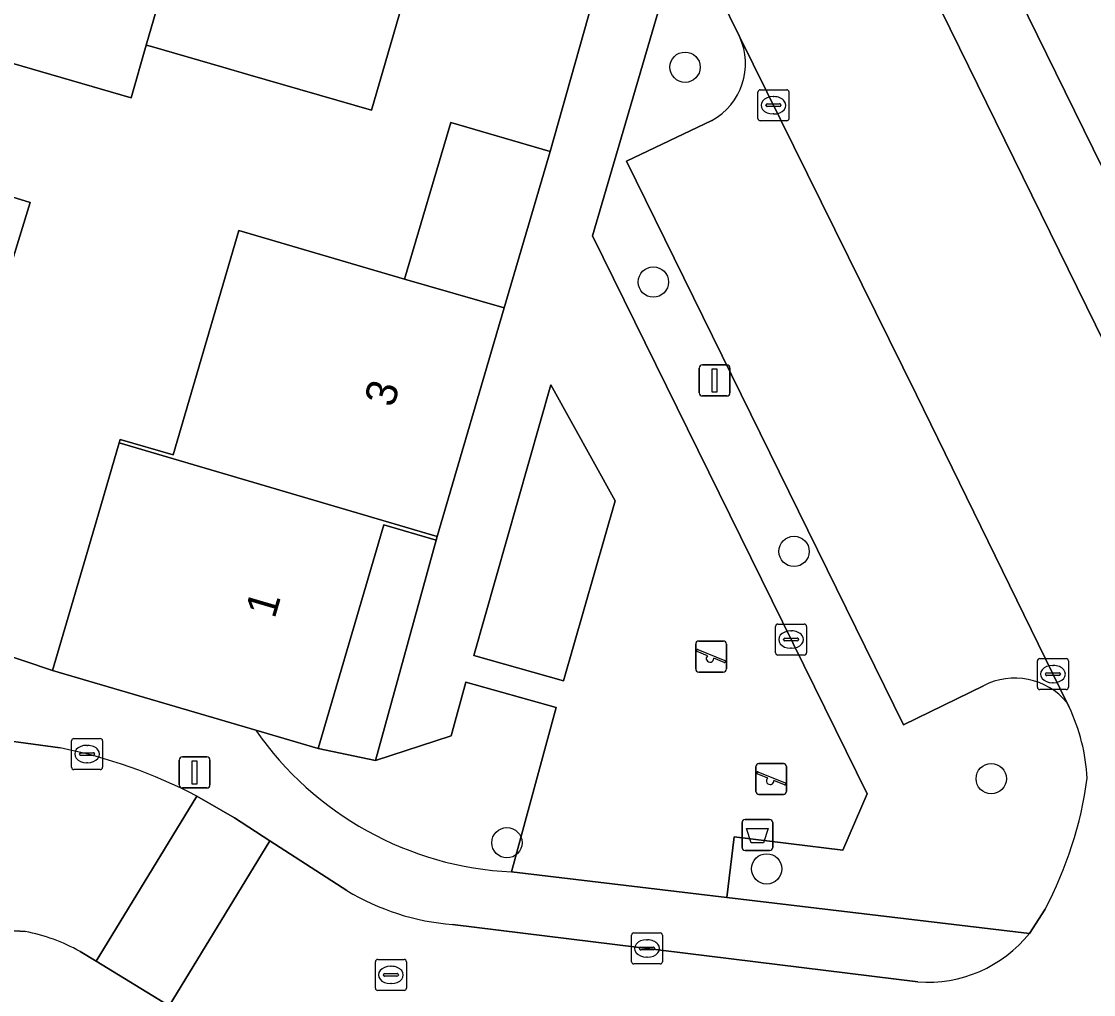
# Model space of a CAD drawing. Extents: x 159716 to 160783, y 383290 to 384031.
# Drawn here: x 160051.81 to 160086.41, y 383383.96 to 383415.36 of the extents above; entities that cross this region are included whole.
import ezdxf

# ---------------------------------------------------------------- set-up
doc = ezdxf.new("R2010")
doc.units = 0
for name, color, linetype in [('IMGEO_Afvalbak', 7, 'Continuous'), ('IMGEO_Boom', 7, 'Continuous'), ('IMGEO_Erf', 7, 'Continuous'), ('IMGEO_Groenvoorziening', 7, 'Continuous'), ('IMGEO_Kolk', 7, 'Continuous'), ('IMGEO_Lichtmast', 7, 'Continuous'), ('IMGEO_Pand', 7, 'Continuous'), ('IMGEO_Pand_nummerreeks', 7, 'Continuous'), ('IMGEO_Parkeervlak_open', 7, 'Continuous'), ('IMGEO_Rijbaan_lokaal_open', 7, 'Continuous'), ('IMGEO_Rioolput', 7, 'Continuous'), ('IMGEO_Speelvoorziening', 7, 'Continuous'), ('IMGEO_Voetpad_open', 7, 'Continuous')]:
    doc.layers.add(name, color=color, linetype=linetype)

msp = doc.modelspace()

# ---------------------------------------------------------------- linework, layer by layer
at = {"layer": 'IMGEO_Afvalbak'}
for p, q in [((160075.166, 383389.612), (160075.956, 383389.612)), ((160075.956, 383389.612), (160075.166, 383389.612)), ((160075.066, 383388.712), (160075.066, 383389.512)), ((160075.066, 383389.512), (160075.066, 383388.712)), ((160076.056, 383389.512), (160076.056, 383388.712)), ((160076.056, 383388.712), (160076.056, 383389.512)), ((160075.956, 383388.612), (160075.166, 383388.612)), ((160075.166, 383388.612), (160075.956, 383388.612))]:
    msp.add_line(p, q, dxfattribs=at)
msp.add_lwpolyline([(160075.209, 383389.326), (160075.913, 383389.326), (160075.764, 383388.856), (160075.358, 383388.856), (160075.209, 383389.326)], dxfattribs=at)
for centre, start, end in [((160075.166, 383389.512), 90, 180), ((160075.166, 383389.512), 90, 180), ((160075.956, 383389.512), 0, 90), ((160075.956, 383389.512), 360, 90), ((160075.166, 383388.712), 180, 270), ((160075.166, 383388.712), 180, 270), ((160075.956, 383388.712), 270, 0), ((160075.956, 383388.712), 270, 0)]:
    msp.add_arc(centre, 0.1, start, end, dxfattribs=at)
at = {"layer": 'IMGEO_Boom'}
for centre in [(160073.229, 383413.882), (160072.206, 383406.951), (160076.745, 383398.261), (160083.107, 383390.929), (160067.48, 383388.863), (160075.861, 383388.02)]:
    msp.add_circle(centre, 0.489, dxfattribs=at)
at = {"layer": 'IMGEO_Erf'}
for points in [[(160080.405, 383423.453), (160097.768, 383388.109)], [(160044.548, 383397.2), (160052.814, 383394.42), (160054.222, 383399.218), (160054.969, 383401.761), (160055.002, 383401.874), (160056.707, 383401.373), (160058.832, 383408.61), (160064.175, 383407.042), (160065.671, 383412.098), (160068.88, 383411.166), (160070.627, 383417.38), (160068.099, 383420.349), (160065.601, 383421.083), (160063.114, 383412.492), (160059.121, 383413.649), (160058.312, 383413.883), (160056.011, 383414.549), (160055.843, 383414.597), (160055.35, 383412.897), (160053.1, 383413.548), (160048.31, 383414.935)], [(160048.536, 383410.614), (160052.099, 383409.518), (160051.183, 383406.541)]]:
    msp.add_lwpolyline(points, dxfattribs=at)
msp.add_lwpolyline([(160065.195, 383398.622), (160063.506, 383399.118), (160061.388, 383391.903), (160063.239, 383391.511)], close=True, dxfattribs=at)
at = {"layer": 'IMGEO_Groenvoorziening'}
for points in [[(160074.989, 383414.871), (160074.348, 383416.169), (160073.789, 383417.331), (160072.664, 383416.709), (160070.246, 383408.439), (160079.102, 383390.437), (160078.317, 383388.621), (160074.813, 383389.05), (160074.573, 383387.094), (160084.344, 383385.936), (160084.845, 383386.721)], [(160082.854, 383393.924), (160080.28, 383392.663), (160071.343, 383410.855), (160074.095, 383412.165)], [(160067.629, 383387.921), (160069.074, 383393.223), (160066.154, 383394.043), (160065.679, 383392.313), (160063.239, 383391.511), (160061.388, 383391.903), (160059.374, 383392.494)], [(160085.62, 383393.242), (160085.552, 383393.382)]]:
    msp.add_lwpolyline(points, dxfattribs=at)
msp.add_lwpolyline([(160069.303, 383394.089), (160070.972, 383399.888), (160068.898, 383403.633), (160066.412, 383394.899)], close=True, dxfattribs=at)
for centre, radius, start, end in [((160073.094, 383413.996), 2.087, 298.6507, 24.7846), ((160083.869, 383391.993), 2.182, 39.5467, 117.7354), ((160080.182, 383390.64), 6.028, 2.8628, 25.5727), ((160068.137, 383398.575), 10.666, 214.7589, 267.2711), ((160073.9, 383392.571), 12.41, 331.8731, 352.4505)]:
    msp.add_arc(centre, radius, start, end, dxfattribs=at)
at = {"layer": 'IMGEO_Kolk'}
for p, q in [((160075.581, 383412.227), (160075.581, 383413.079)), ((160075.656, 383413.153), (160076.508, 383413.153)), ((160076.582, 383413.079), (160076.582, 383412.227)), ((160075.883, 383412.696), (160076.281, 383412.696)), ((160076.069, 383412.933), (160076.094, 383412.933)), ((160075.84, 383412.647), (160075.84, 383412.659)), ((160076.278, 383412.61), (160075.88, 383412.61)), ((160076.092, 383412.373), (160076.067, 383412.373)), ((160076.324, 383412.659), (160076.324, 383412.647)), ((160076.508, 383412.153), (160075.656, 383412.153)), ((160076.15, 383394.991), (160076.15, 383395.843)), ((160076.225, 383395.917), (160077.077, 383395.917)), ((160077.151, 383395.843), (160077.151, 383394.991)), ((160076.409, 383395.411), (160076.409, 383395.423)), ((160076.452, 383395.46), (160076.85, 383395.46)), ((160076.638, 383395.697), (160076.663, 383395.697)), ((160076.893, 383395.423), (160076.893, 383395.411)), ((160076.847, 383395.374), (160076.449, 383395.374)), ((160076.661, 383395.137), (160076.636, 383395.137)), ((160077.077, 383394.917), (160076.225, 383394.917)), ((160084.598, 383393.877), (160084.598, 383394.729)), ((160084.673, 383394.803), (160085.525, 383394.803)), ((160085.599, 383394.729), (160085.599, 383393.877)), ((160085.086, 383394.583), (160085.111, 383394.583)), ((160084.857, 383394.297), (160084.857, 383394.309)), ((160085.295, 383394.26), (160084.897, 383394.26)), ((160084.9, 383394.346), (160085.298, 383394.346)), ((160085.109, 383394.023), (160085.084, 383394.023)), ((160085.341, 383394.309), (160085.341, 383394.297)), ((160085.525, 383393.803), (160084.673, 383393.803)), ((160053.433, 383391.298), (160053.433, 383392.15)), ((160053.508, 383392.224), (160054.36, 383392.224)), ((160053.921, 383392.004), (160053.946, 383392.004)), ((160054.434, 383392.15), (160054.434, 383391.298)), ((160053.692, 383391.718), (160053.692, 383391.73)), ((160054.13, 383391.681), (160053.732, 383391.681)), ((160053.735, 383391.767), (160054.133, 383391.767)), ((160054.176, 383391.73), (160054.176, 383391.718)), ((160053.944, 383391.444), (160053.919, 383391.444)), ((160054.36, 383391.224), (160053.508, 383391.224)), ((160071.5, 383385.025), (160071.5, 383385.877)), ((160071.575, 383385.951), (160072.427, 383385.951)), ((160071.988, 383385.731), (160072.013, 383385.731)), ((160072.501, 383385.877), (160072.501, 383385.025)), ((160071.759, 383385.445), (160071.759, 383385.457)), ((160072.197, 383385.408), (160071.799, 383385.408)), ((160071.802, 383385.494), (160072.2, 383385.494)), ((160072.243, 383385.457), (160072.243, 383385.445)), ((160072.011, 383385.171), (160071.986, 383385.171)), ((160072.427, 383384.951), (160071.575, 383384.951))]:
    msp.add_line(p, q, dxfattribs=at)
for points in [[(160075.581, 383412.227), (160075.581, 383413.079)], [(160075.656, 383413.153), (160076.508, 383413.153)], [(160076.582, 383413.079), (160076.582, 383412.227)], [(160076.508, 383412.153), (160075.656, 383412.153)], [(160076.15, 383394.991), (160076.15, 383395.843)], [(160076.225, 383395.917), (160077.077, 383395.917)], [(160077.151, 383395.843), (160077.151, 383394.991)], [(160077.077, 383394.917), (160076.225, 383394.917)], [(160084.598, 383393.877), (160084.598, 383394.729)], [(160084.673, 383394.803), (160085.525, 383394.803)], [(160085.599, 383394.729), (160085.599, 383393.877)], [(160085.525, 383393.803), (160084.673, 383393.803)], [(160053.433, 383391.298), (160053.433, 383392.15)], [(160053.508, 383392.224), (160054.36, 383392.224)], [(160054.434, 383392.15), (160054.434, 383391.298)], [(160054.36, 383391.224), (160053.508, 383391.224)], [(160071.5, 383385.025), (160071.5, 383385.877)], [(160071.575, 383385.951), (160072.427, 383385.951)], [(160072.501, 383385.877), (160072.501, 383385.025)], [(160072.427, 383384.951), (160071.575, 383384.951)]]:
    msp.add_lwpolyline(points, dxfattribs=at)
for centre, radius, start, end in [((160075.658, 383413.077), 0.0765, 91.552, 178.448), ((160075.658, 383413.077), 0.0765, 91.552, 178.448), ((160076.506, 383413.077), 0.0765, 1.552, 88.448), ((160076.506, 383413.077), 0.0765, 1.552, 88.448), ((160075.88, 383412.656), 0.0403, 85.8775, 175.7526), ((160076.285, 383412.658), 0.0386, 1.7309, 96.639), ((160075.877, 383412.646), 0.0366, 178.938, 274.7102), ((160076.281, 383412.653), 0.043, 264.8664, 352.4533), ((160075.658, 383412.229), 0.0765, 181.552, 268.448), ((160075.658, 383412.229), 0.0765, 181.552, 268.448), ((160076.506, 383412.229), 0.0765, 271.552, 358.448), ((160076.506, 383412.229), 0.0765, 271.552, 358.448), ((160076.227, 383395.841), 0.0765, 91.552, 178.448), ((160076.227, 383395.841), 0.0765, 91.552, 178.448), ((160077.075, 383395.841), 0.0765, 1.552, 88.448), ((160077.075, 383395.841), 0.0765, 1.552, 88.448), ((160076.449, 383395.42), 0.0403, 85.8775, 175.7526), ((160076.446, 383395.41), 0.0366, 178.938, 274.7102), ((160076.85, 383395.417), 0.043, 264.8664, 352.4533), ((160076.854, 383395.422), 0.0386, 1.7309, 96.639), ((160076.227, 383394.993), 0.0765, 181.552, 268.448), ((160076.227, 383394.993), 0.0765, 181.552, 268.448), ((160077.075, 383394.993), 0.0765, 271.552, 358.448), ((160077.075, 383394.993), 0.0765, 271.552, 358.448), ((160084.675, 383394.727), 0.0765, 91.552, 178.448), ((160084.675, 383394.727), 0.0765, 91.552, 178.448), ((160085.523, 383394.727), 0.0765, 1.552, 88.448), ((160085.523, 383394.727), 0.0765, 1.552, 88.448), ((160084.897, 383394.306), 0.0403, 85.8775, 175.7526), ((160084.894, 383394.296), 0.0366, 178.938, 274.7102), ((160085.298, 383394.303), 0.043, 264.8664, 352.4533), ((160085.302, 383394.308), 0.0386, 1.7309, 96.639), ((160084.675, 383393.879), 0.0765, 181.552, 268.448), ((160084.675, 383393.879), 0.0765, 181.552, 268.448), ((160085.523, 383393.879), 0.0765, 271.552, 358.448), ((160085.523, 383393.879), 0.0765, 271.552, 358.448), ((160053.51, 383392.148), 0.0765, 91.552, 178.448), ((160053.51, 383392.148), 0.0765, 91.552, 178.448), ((160054.358, 383392.148), 0.0765, 1.552, 88.448), ((160054.358, 383392.148), 0.0765, 1.552, 88.448), ((160053.732, 383391.727), 0.0403, 85.8775, 175.7526), ((160053.729, 383391.717), 0.0366, 178.938, 274.7102), ((160054.133, 383391.724), 0.043, 264.8664, 352.4533), ((160054.137, 383391.729), 0.0386, 1.7309, 96.639), ((160053.51, 383391.3), 0.0765, 181.552, 268.448), ((160053.51, 383391.3), 0.0765, 181.552, 268.448), ((160054.358, 383391.3), 0.0765, 271.552, 358.448), ((160054.358, 383391.3), 0.0765, 271.552, 358.448), ((160071.577, 383385.875), 0.0765, 91.552, 178.448), ((160071.577, 383385.875), 0.0765, 91.552, 178.448), ((160072.425, 383385.875), 0.0765, 1.552, 88.448), ((160072.425, 383385.875), 0.0765, 1.552, 88.448), ((160071.799, 383385.454), 0.0403, 85.8775, 175.7526), ((160071.796, 383385.444), 0.0366, 178.938, 274.7102), ((160072.2, 383385.451), 0.043, 264.8664, 352.4533), ((160072.204, 383385.456), 0.0386, 1.7309, 96.639), ((160071.577, 383385.027), 0.0765, 181.552, 268.448), ((160071.577, 383385.027), 0.0765, 181.552, 268.448), ((160072.425, 383385.027), 0.0765, 271.552, 358.448), ((160072.425, 383385.027), 0.0765, 271.552, 358.448)]:
    msp.add_arc(centre, radius, start, end, dxfattribs=at)
for centre, major_axis, ratio, start_param, end_param in [((160076.068, 383412.653), (-0.387, 0.002), 0.722429, 4.712389, 7.853982), ((160076.093, 383412.653), (-0.39, 0.002), 0.717154, 1.570796, 4.712389), ((160076.637, 383395.417), (-0.387, 0.002), 0.722429, 4.712389, 7.853982), ((160076.662, 383395.417), (-0.39, 0.002), 0.717154, 1.570796, 4.712389), ((160085.085, 383394.303), (-0.387, 0.002), 0.722429, 4.712389, 7.853982), ((160085.11, 383394.303), (-0.39, 0.002), 0.717154, 1.570796, 4.712389), ((160053.92, 383391.724), (-0.387, 0.002), 0.722429, 4.712389, 7.853982), ((160053.945, 383391.724), (-0.39, 0.002), 0.717154, 1.570796, 4.712389), ((160071.987, 383385.451), (-0.387, 0.002), 0.722429, 4.712389, 7.853982), ((160072.012, 383385.451), (-0.39, 0.002), 0.717154, 1.570796, 4.712389)]:
    msp.add_ellipse(centre, major_axis=major_axis, ratio=ratio, start_param=start_param, end_param=end_param, dxfattribs=at)
at = {"layer": 'IMGEO_Lichtmast'}
for p, q in [((160073.687, 383403.375), (160073.687, 383404.175)), ((160073.687, 383404.175), (160073.687, 383403.375)), ((160073.787, 383404.275), (160074.577, 383404.275)), ((160074.577, 383404.275), (160073.787, 383404.275)), ((160074.677, 383404.175), (160074.677, 383403.375)), ((160074.677, 383403.375), (160074.677, 383404.175)), ((160074.577, 383403.275), (160073.787, 383403.275)), ((160073.787, 383403.275), (160074.577, 383403.275)), ((160057.008, 383391.629), (160057.798, 383391.629)), ((160057.798, 383391.629), (160057.008, 383391.629)), ((160056.908, 383390.729), (160056.908, 383391.529)), ((160056.908, 383391.529), (160056.908, 383390.729)), ((160057.898, 383391.529), (160057.898, 383390.729)), ((160057.898, 383390.729), (160057.898, 383391.529)), ((160057.798, 383390.629), (160057.008, 383390.629)), ((160057.008, 383390.629), (160057.798, 383390.629))]:
    msp.add_line(p, q, dxfattribs=at)
for points in [[(160074.107, 383404.15), (160074.257, 383404.15), (160074.257, 383403.4), (160074.107, 383403.4), (160074.107, 383404.15)], [(160057.328, 383391.504), (160057.478, 383391.504), (160057.478, 383390.754), (160057.328, 383390.754), (160057.328, 383391.504)]]:
    msp.add_lwpolyline(points, dxfattribs=at)
for centre, start, end in [((160073.787, 383404.175), 90, 180), ((160073.787, 383404.175), 90, 180), ((160074.577, 383404.175), 0, 90), ((160074.577, 383404.175), 360, 90), ((160073.787, 383403.375), 180, 270), ((160073.787, 383403.375), 180, 270), ((160074.577, 383403.375), 270, 0), ((160074.577, 383403.375), 270, 0), ((160057.008, 383391.529), 90, 180), ((160057.008, 383391.529), 90, 180), ((160057.798, 383391.529), 0, 90), ((160057.798, 383391.529), 360, 90), ((160057.008, 383390.729), 180, 270), ((160057.008, 383390.729), 180, 270), ((160057.798, 383390.729), 270, 0), ((160057.798, 383390.729), 270, 0)]:
    msp.add_arc(centre, 0.1, start, end, dxfattribs=at)
at = {"layer": 'IMGEO_Pand'}
for points in [[(160057.84, 383421.479), (160057.713, 383421.516), (160056.413, 383421.892), (160050.589, 383423.578), (160050.101, 383421.821), (160048.2, 383414.967), (160048.31, 383414.935), (160053.1, 383413.548), (160055.35, 383412.897), (160055.843, 383414.597)], [(160065.601, 383421.083), (160058.335, 383423.186), (160057.84, 383421.479), (160055.843, 383414.597), (160056.011, 383414.549), (160058.312, 383413.883), (160059.121, 383413.649), (160063.114, 383412.492)], [(160064.175, 383407.042), (160067.395, 383406.115), (160068.88, 383411.166), (160065.671, 383412.098)], [(160051.183, 383406.541), (160052.099, 383409.518), (160048.536, 383410.614), (160047.62, 383407.637)], [(160065.231, 383398.745), (160067.395, 383406.115), (160064.175, 383407.042), (160058.832, 383408.61), (160056.707, 383401.373), (160055.002, 383401.874), (160054.969, 383401.761)], [(160065.231, 383398.745), (160054.969, 383401.761), (160054.222, 383399.218), (160052.814, 383394.42), (160059.374, 383392.494), (160061.388, 383391.903), (160063.506, 383399.118), (160065.195, 383398.622)]]:
    msp.add_lwpolyline(points, close=True, dxfattribs=at)
at = {"layer": 'IMGEO_Parkeervlak_open'}
for points in [[(160085.552, 383393.382), (160080.692, 383403.311), (160074.989, 383414.871)], [(160074.095, 383412.165), (160071.343, 383410.855), (160080.28, 383392.663), (160082.854, 383393.924)]]:
    msp.add_lwpolyline(points, dxfattribs=at)
for centre, radius, start, end in [((160073.094, 383413.996), 2.087, 298.6507, 24.7846), ((160083.869, 383391.993), 2.182, 39.5467, 117.7354)]:
    msp.add_arc(centre, radius, start, end, dxfattribs=at)
at = {"layer": 'IMGEO_Rijbaan_lokaal_open'}
for points in [[(160089.692, 383399.019), (160078.272, 383422.273), (160077.081, 383424.063)], [(160073.789, 383417.331), (160074.348, 383416.169), (160074.989, 383414.871), (160080.692, 383403.311), (160085.552, 383393.382), (160085.62, 383393.242)], [(160053.062, 383391.922), (160044.505, 383393.088), (160031.637, 383394.841)], [(160053.707, 383385.356), (160054.225, 383385.04), (160057.472, 383390.367)], [(160062.314, 383387.323), (160059.828, 383388.929), (160056.582, 383383.604), (160059.007, 383382.126)], [(160030.94, 383388.777), (160051.595, 383386.022), (160051.765, 383386.007), (160051.935, 383385.999)], [(160084.845, 383386.721), (160084.344, 383385.936)], [(160080.742, 383384.372), (160065.722, 383386.224)]]:
    msp.add_lwpolyline(points, dxfattribs=at)
msp.add_lwpolyline([(160056.582, 383383.604), (160059.828, 383388.929), (160058.685, 383389.668), (160057.472, 383390.367), (160054.225, 383385.04)], close=True, dxfattribs=at)
for centre, radius, start, end in [((160080.182, 383390.64), 6.028, 2.8628, 25.5727), ((160049.815, 383375.683), 16.56, 62.4604, 78.6935), ((160073.9, 383392.571), 12.41, 331.8731, 352.4505), ((160066.345, 383393.988), 7.789, 238.838, 265.4154), ((160050.817, 383380.156), 5.949, 60.9396, 79.1721), ((160081.049, 383388.595), 4.234, 265.8404, 321.1008)]:
    msp.add_arc(centre, radius, start, end, dxfattribs=at)
at = {"layer": 'IMGEO_Rioolput'}
for p, q in [((160063.235, 383384.172), (160063.235, 383385.024)), ((160063.31, 383385.098), (160064.162, 383385.098)), ((160064.236, 383385.024), (160064.236, 383384.172)), ((160063.723, 383384.878), (160063.748, 383384.878)), ((160063.494, 383384.592), (160063.494, 383384.604)), ((160063.932, 383384.555), (160063.534, 383384.555)), ((160063.537, 383384.641), (160063.935, 383384.641)), ((160063.978, 383384.604), (160063.978, 383384.592)), ((160064.162, 383384.098), (160063.31, 383384.098)), ((160063.746, 383384.318), (160063.721, 383384.318))]:
    msp.add_line(p, q, dxfattribs=at)
for points in [[(160063.235, 383384.172), (160063.235, 383385.024)], [(160063.31, 383385.098), (160064.162, 383385.098)], [(160064.236, 383385.024), (160064.236, 383384.172)], [(160064.162, 383384.098), (160063.31, 383384.098)]]:
    msp.add_lwpolyline(points, dxfattribs=at)
for centre, radius, start, end in [((160063.312, 383385.022), 0.0765, 91.552, 178.448), ((160063.312, 383385.022), 0.0765, 91.552, 178.448), ((160064.16, 383385.022), 0.0765, 1.552, 88.448), ((160064.16, 383385.022), 0.0765, 1.552, 88.448), ((160063.534, 383384.601), 0.0403, 85.8775, 175.7526), ((160063.531, 383384.591), 0.0366, 178.938, 274.7102), ((160063.935, 383384.598), 0.043, 264.8664, 352.4533), ((160063.939, 383384.603), 0.0386, 1.7309, 96.639), ((160063.312, 383384.174), 0.0765, 181.552, 268.448), ((160063.312, 383384.174), 0.0765, 181.552, 268.448), ((160064.16, 383384.174), 0.0765, 271.552, 358.448), ((160064.16, 383384.174), 0.0765, 271.552, 358.448)]:
    msp.add_arc(centre, radius, start, end, dxfattribs=at)
for centre, major_axis, ratio, start_param, end_param in [((160063.722, 383384.598), (-0.387, 0.002), 0.722429, 4.712389, 7.853982), ((160063.747, 383384.598), (-0.39, 0.002), 0.717154, 1.570796, 4.712389)]:
    msp.add_ellipse(centre, major_axis=major_axis, ratio=ratio, start_param=start_param, end_param=end_param, dxfattribs=at)
at = {"layer": 'IMGEO_Speelvoorziening'}
for p, q in [((160073.571, 383394.468), (160073.571, 383395.268)), ((160073.571, 383395.268), (160073.571, 383394.468)), ((160073.64, 383395.093), (160074.516, 383394.74)), ((160073.671, 383395.368), (160074.461, 383395.368)), ((160074.461, 383395.368), (160073.671, 383395.368)), ((160074.561, 383395.268), (160074.561, 383394.468)), ((160074.561, 383394.468), (160074.561, 383395.268)), ((160073.954, 383394.896), (160073.615, 383395.033)), ((160074.492, 383394.68), (160074.152, 383394.817)), ((160074.461, 383394.368), (160073.671, 383394.368)), ((160073.671, 383394.368), (160074.461, 383394.368)), ((160075.513, 383390.52), (160075.513, 383391.32)), ((160075.513, 383391.32), (160075.513, 383390.52)), ((160075.613, 383391.42), (160076.403, 383391.42)), ((160076.403, 383391.42), (160075.613, 383391.42)), ((160076.503, 383391.32), (160076.503, 383390.52)), ((160076.503, 383390.52), (160076.503, 383391.32)), ((160075.896, 383390.948), (160075.557, 383391.085)), ((160075.582, 383391.145), (160076.458, 383390.792)), ((160076.434, 383390.732), (160076.094, 383390.869)), ((160076.403, 383390.42), (160075.613, 383390.42)), ((160075.613, 383390.42), (160076.403, 383390.42))]:
    msp.add_line(p, q, dxfattribs=at)
for centre, radius, start, end in [((160073.671, 383395.268), 0.1, 90, 180), ((160073.671, 383395.268), 0.1, 90, 180), ((160073.628, 383395.063), 0.0327, 68.078, 248.078), ((160074.461, 383395.268), 0.1, 0, 90), ((160074.461, 383395.268), 0.1, 360, 90), ((160074.033, 383394.806), 0.12, 130.9928, 5.1632), ((160074.504, 383394.71), 0.0327, 248.078, 68.078), ((160073.671, 383394.468), 0.1, 180, 270), ((160073.671, 383394.468), 0.1, 180, 270), ((160074.461, 383394.468), 0.1, 270, 0), ((160074.461, 383394.468), 0.1, 270, 0), ((160075.613, 383391.32), 0.1, 90, 180), ((160075.613, 383391.32), 0.1, 90, 180), ((160076.403, 383391.32), 0.1, 0, 90), ((160076.403, 383391.32), 0.1, 360, 90), ((160075.57, 383391.115), 0.0327, 68.078, 248.078), ((160075.975, 383390.858), 0.12, 130.9928, 5.1632), ((160076.446, 383390.762), 0.0327, 248.078, 68.078), ((160075.613, 383390.52), 0.1, 180, 270), ((160075.613, 383390.52), 0.1, 180, 270), ((160076.403, 383390.52), 0.1, 270, 0), ((160076.403, 383390.52), 0.1, 270, 0)]:
    msp.add_arc(centre, radius, start, end, dxfattribs=at)
at = {"layer": 'IMGEO_Voetpad_open'}
for points in [[(160069.173, 383429.702), (160072.625, 383427.835), (160074.442, 383426.665), (160074.767, 383427.04), (160077.431, 383424.419), (160077.081, 383424.063), (160078.272, 383422.273), (160089.692, 383399.019)], [(160097.768, 383388.109), (160080.405, 383423.453)], [(160059.374, 383392.494), (160052.814, 383394.42), (160044.548, 383397.2), (160043.108, 383397.684), (160041.813, 383398.119), (160033.088, 383399.276), (160032.2, 383399.447)], [(160044.505, 383393.088), (160053.062, 383391.922)], [(160057.472, 383390.367), (160058.685, 383389.668), (160059.828, 383388.929), (160062.314, 383387.323)], [(160084.344, 383385.936), (160074.573, 383387.094), (160067.629, 383387.921)], [(160065.722, 383386.224), (160080.742, 383384.372)], [(160051.935, 383385.999), (160051.765, 383386.007), (160051.595, 383386.022)], [(160059.007, 383382.126), (160056.582, 383383.604), (160054.225, 383385.04), (160053.707, 383385.356)]]:
    msp.add_lwpolyline(points, dxfattribs=at)
for points in [[(160070.246, 383408.439), (160072.664, 383416.709), (160070.627, 383417.38), (160068.88, 383411.166), (160067.395, 383406.115), (160065.231, 383398.745), (160065.195, 383398.622), (160063.239, 383391.511), (160065.679, 383392.313), (160066.154, 383394.043), (160069.074, 383393.223), (160067.629, 383387.921), (160074.573, 383387.094), (160074.813, 383389.05), (160078.317, 383388.621), (160079.102, 383390.437)], [(160069.303, 383394.089), (160066.412, 383394.899), (160068.898, 383403.633), (160070.972, 383399.888)]]:
    msp.add_lwpolyline(points, close=True, dxfattribs=at)
for centre, radius, start, end in [((160068.137, 383398.575), 10.666, 214.7589, 267.2711), ((160049.815, 383375.683), 16.56, 62.4604, 78.6935), ((160066.345, 383393.988), 7.789, 238.838, 265.4154), ((160050.817, 383380.156), 5.949, 60.9396, 79.1721), ((160081.049, 383388.595), 4.234, 265.8404, 321.1008)]:
    msp.add_arc(centre, radius, start, end, dxfattribs=at)

# ---------------------------------------------------------------- texts
at = {"layer": 'IMGEO_Pand_nummerreeks'}
for s, rotation, p in [('3', 73.6374, (160063.818, 383402.875)), ('1', 73.6401, (160059.983, 383396.065))]:
    msp.add_text(s, height=1, rotation=rotation, dxfattribs=at).set_placement(p)

doc.saveas('drawing.dxf')
